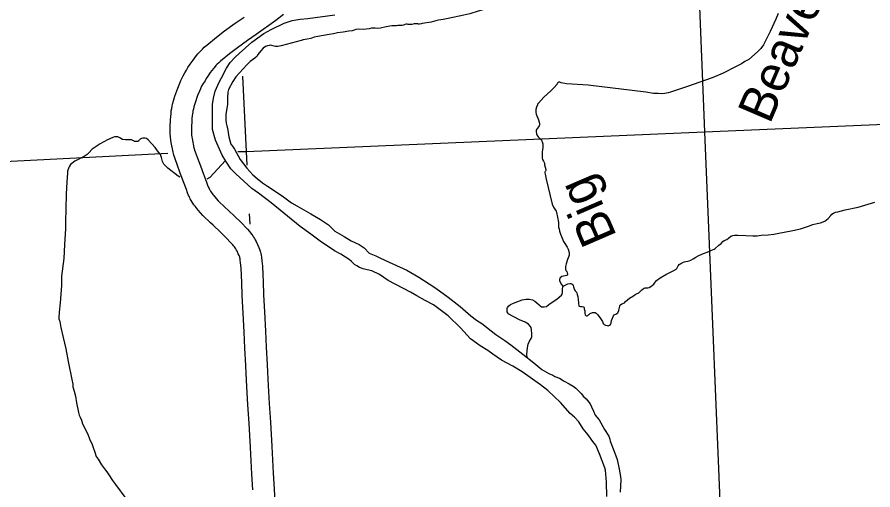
# Model space of a CAD drawing. Extents: x 1720274 to 1751788, y 372074 to 391887.
# Drawn here: x 1737987 to 1739571, y 379057 to 379933 of the extents above; entities that cross this region are included whole.
import ezdxf

# ---------------------------------------------------------------- set-up
doc = ezdxf.new("R2010")
doc.units = 0
for name, color, linetype in [('Level 10', 7, 'Continuous'), ('Level 35', 7, 'Continuous'), ('Level 5', 7, 'Continuous'), ('Level 9', 7, 'Continuous')]:
    doc.layers.add(name, color=color, linetype=linetype)

msp = doc.modelspace()

# ---------------------------------------------------------------- linework, layer by layer
at = {"layer": 'Level 10'}
for points in [[(1738479.8, 379937.6), (1738466, 379926.9), (1738429.6, 379900.7), (1738413.4, 379889.6), (1738394.6, 379875.9), (1738380.2, 379864.9), (1738363.6, 379851.3), (1738360.1, 379848.1), (1738357.5, 379845.6), (1738354.9, 379843), (1738351.4, 379839.2), (1738350.3, 379837.8), (1738344.5, 379830.1), (1738339.8, 379823.4), (1738336.9, 379819), (1738334.7, 379815.1), (1738331.5, 379809.7), (1738328.5, 379804.7), (1738327.1, 379802), (1738326.2, 379799.9), (1738324.4, 379795.6), (1738321.1, 379787.6), (1738316.6, 379774.2), (1738314.2, 379767), (1738313.2, 379762.5), (1738312.4, 379759.4), (1738311.9, 379757.1), (1738311.5, 379753.9), (1738311.1, 379750.7), (1738310.6, 379745.3), (1738310.3, 379741.3), (1738309.7, 379728.2), (1738309.7, 379717.9), (1738309.9, 379714.9), (1738310.4, 379710.7), (1738310.9, 379707.8), (1738314.3, 379691), (1738314.8, 379688.9), (1738315.1, 379687.7), (1738315.5, 379686.4), (1738316.6, 379683.2), (1738320.1, 379673.5), (1738326.1, 379657.2), (1738331.6, 379641.8), (1738337.2, 379627.3), (1738339.3, 379621.7), (1738340.6, 379618.4), (1738341.1, 379617.4), (1738342.2, 379615.3), (1738343.1, 379613.3), (1738343.4, 379612.7), (1738344, 379611.7), (1738344.9, 379610.3), (1738346.2, 379608.6), (1738347.9, 379606.3), (1738349.4, 379604.4), (1738351, 379602.2), (1738352.2, 379600.8), (1738359.1, 379592.7), (1738372.1, 379580.5), (1738377.3, 379575.5), (1738390.5, 379562.7), (1738400.2, 379553.4), (1738413.4, 379540.3), (1738417.1, 379535.7), (1738419, 379533.3), (1738421.2, 379530.3), (1738423.1, 379527.7), (1738424.6, 379525.3), (1738426.1, 379522.9), (1738427.8, 379520.1), (1738429.3, 379517.1), (1738432, 379511.8), (1738434.5, 379506.3), (1738435.7, 379503), (1738436.9, 379499.4), (1738437.5, 379497.2), (1738438.1, 379494.7), (1738438.6, 379492.2), (1738439.2, 379488.3), (1738440, 379481.7), (1738441, 379471.3), (1738441.9, 379456.1), (1738442.4, 379442.7)], [(1738402.9, 379441.1), (1738402.4, 379454.2), (1738401.7, 379468.2), (1738400.7, 379477.4), (1738400.1, 379482.6), (1738399.7, 379484.9), (1738399.4, 379486.8), (1738399.2, 379487.7), (1738399.1, 379487.9), (1738398.5, 379489.8), (1738398, 379491.1), (1738396.4, 379494.6), (1738394, 379499.3), (1738392.9, 379501.4), (1738392.4, 379502.3), (1738391.5, 379503.8), (1738390.3, 379505.6), (1738389.2, 379507.2), (1738387.7, 379509.2), (1738386.2, 379511.1), (1738384, 379513.8), (1738372.6, 379525.1), (1738363.1, 379534.2), (1738349.7, 379547.2), (1738344.8, 379552), (1738330.5, 379565.4), (1738321.8, 379575.5), (1738320, 379577.8), (1738318.1, 379580.2), (1738316.4, 379582.4), (1738314.2, 379585.4), (1738312.3, 379588), (1738310.9, 379590.2), (1738308.9, 379593.3), (1738307.4, 379596.4), (1738306.8, 379597.7), (1738305.7, 379599.7), (1738304.4, 379602.5), (1738302.4, 379607.4), (1738300.3, 379613.3), (1738294.6, 379628), (1738289, 379643.8), (1738283, 379660), (1738279.3, 379670.2), (1738278, 379673.9), (1738277.1, 379676.9), (1738276.3, 379680.1), (1738275.7, 379682.9), (1738272, 379700.7), (1738271.3, 379705.2), (1738270.6, 379711.2), (1738270.2, 379716.5), (1738270.1, 379729.1), (1738270.9, 379743.5), (1738271.2, 379748.4), (1738271.9, 379755.2), (1738272.3, 379759.1), (1738273, 379763.5), (1738273.8, 379767.7), (1738274.8, 379771.8), (1738276.2, 379777.7), (1738279.1, 379786.6), (1738284.1, 379801.5), (1738287.9, 379810.6), (1738289.8, 379815.3), (1738291.5, 379819.2), (1738294, 379824), (1738297.5, 379829.9), (1738300.5, 379834.9), (1738303.2, 379839.6), (1738307.1, 379845.5), (1738312.6, 379853.4), (1738319.1, 379862), (1738321.4, 379864.9), (1738326.2, 379870.1), (1738329.8, 379873.8), (1738333.3, 379877.1), (1738337.8, 379881.2), (1738355.7, 379895.8), (1738371, 379907.6), (1738390.6, 379921.8), (1738406.9, 379933)], [(1738423.2, 379056.9), (1738421.7, 379086.1), (1738418.8, 379135.3), (1738416.5, 379180.4), (1738414.3, 379214.4), (1738412.4, 379248.3), (1738411.2, 379272.7), (1738410.3, 379287.3), (1738408.5, 379319.7), (1738407.2, 379349.2), (1738405.4, 379384.7), (1738403.8, 379416.9), (1738402.9, 379441.1)], [(1738442.4, 379442.7), (1738443.3, 379418.6), (1738444.9, 379386.7), (1738446.6, 379351.1), (1738448, 379321.7), (1738449.7, 379289.6), (1738450.6, 379274.9), (1738451.8, 379250.4), (1738453.7, 379216.8), (1738455.9, 379182.8), (1738458.3, 379137.5), (1738461.1, 379088.3), (1738462.6, 379058.9), (1738464.5, 379021)]]:
    msp.add_lwpolyline(points, dxfattribs=at)
at = {"layer": 'Level 35'}
for points in [[(1739396.2, 379939.4), (1739391.8, 379929.2), (1739381, 379906.5), (1739371.9, 379887.5), (1739368.9, 379881.7), (1739363.9, 379874.8), (1739357.6, 379868.7), (1739341.8, 379854.6), (1739334.4, 379850.7), (1739328, 379846.6), (1739315.9, 379840), (1739294.1, 379829.2), (1739273.7, 379820.4), (1739228.1, 379804.6), (1739196.9, 379793.8), (1739192, 379792.7), (1739185.9, 379791.4), (1739180.1, 379790.8), (1739173.8, 379791.1), (1739165.2, 379791.6), (1739151.1, 379793.6), (1739044.1, 379807.1), (1739004, 379809.6), (1738994.4, 379811.2), (1738991.6, 379812.1), (1738990.4, 379812.3), (1738989.5, 379812.1), (1738987.8, 379811.4), (1738987, 379810.7), (1738985.9, 379808.2), (1738981.2, 379802.3), (1738974.7, 379795.6), (1738962.2, 379784.6), (1738952.2, 379773.4), (1738950.6, 379771.7), (1738950.1, 379770.1), (1738948.3, 379766.3), (1738947, 379761.8), (1738947, 379760.2), (1738947, 379759.5), (1738947.1, 379757), (1738948.1, 379752.9), (1738952.1, 379742.9), (1738953.6, 379738.1), (1738954, 379736.3), (1738954, 379734.6), (1738953.9, 379733), (1738953.3, 379731.2), (1738952.3, 379729.7), (1738950.2, 379727), (1738948.5, 379724.7), (1738948.1, 379722.8), (1738948, 379720.6), (1738948.4, 379716.4), (1738949.5, 379713.7), (1738951.4, 379711.2), (1738953.5, 379709.5), (1738956.3, 379706.7), (1738957.5, 379704.8), (1738959.7, 379699.8), (1738960.1, 379698.2), (1738960.1, 379695.4), (1738960.1, 379691.6), (1738959.5, 379686.8), (1738958.7, 379683.1), (1738958.8, 379680.5), (1738959, 379672.8), (1738959.2, 379671.3), (1738959.9, 379669.3), (1738961.6, 379666.2), (1738962.8, 379663.8), (1738963.2, 379662.3), (1738963.5, 379659.2), (1738964.4, 379655.2), (1738965.7, 379650.6), (1738965.7, 379649), (1738965.3, 379647.5), (1738964.4, 379646.6), (1738964, 379645.5), (1738964, 379644.5), (1738964.4, 379642.1), (1738966.7, 379632.8), (1738977.8, 379586.4), (1738979.9, 379581.1), (1738982.5, 379577.1), (1738984.7, 379573.2), (1738985.7, 379570.7), (1738987.4, 379562.2), (1738989.1, 379552.3), (1738989.5, 379543.7), (1738990.4, 379540.6), (1738991.3, 379536.3), (1738992.9, 379530.8)], [(1738287.9, 379636.7), (1738285.2, 379638.1), (1738265.9, 379653.2), (1738258.6, 379660.6), (1738256, 379665.3), (1738254.2, 379672.7), (1738252, 379678.2), (1738248.3, 379682.8), (1738242.1, 379691.4), (1738229.2, 379705.3), (1738226.2, 379707.8), (1738223.8, 379708.6), (1738221.9, 379708.8), (1738219.5, 379708.6), (1738216.9, 379708), (1738214.7, 379706.9), (1738213.9, 379706.1), (1738212.9, 379704.7), (1738212.1, 379703.7), (1738210.3, 379702.7), (1738209.6, 379702.5), (1738207.2, 379702.5), (1738204.4, 379702.7), (1738203, 379703.5), (1738201.2, 379704.3), (1738198.8, 379705.3), (1738197.8, 379705.5), (1738194.3, 379705.5), (1738191.1, 379705.5), (1738187.7, 379705.5), (1738181.8, 379706.3), (1738179, 379707.8), (1738176.8, 379709.2), (1738174.4, 379710.4), (1738173, 379711.2), (1738172.2, 379711.2), (1738169.2, 379711.2), (1738167.1, 379711), (1738164.1, 379709.8), (1738154.2, 379705.5), (1738140.3, 379697.9), (1738125.6, 379688), (1738119.6, 379681.6), (1738116.6, 379678.4), (1738110.7, 379674.9), (1738100, 379669.3), (1738093.4, 379666.1), (1738087.8, 379661.5), (1738085.9, 379659.6), (1738083.9, 379657), (1738082.7, 379654.4), (1738079.9, 379647.8), (1738079.9, 379643.7), (1738078.9, 379627.8), (1738077.5, 379605.1), (1738076.7, 379577.7), (1738076.3, 379554), (1738076.5, 379547.1), (1738076.1, 379540.5), (1738074.3, 379511.5), (1738073, 379485.5), (1738069.2, 379452.7), (1738069, 379446.7), (1738069, 379440.8), (1738069, 379435.8), (1738067.6, 379419.5), (1738066.2, 379403.6), (1738064.8, 379386.3), (1738064, 379376.4), (1738064.2, 379374.2), (1738065.8, 379368.8), (1738068, 379358.1), (1738072.2, 379339.4), (1738077.1, 379318.1), (1738081.3, 379294.7), (1738088.4, 379261.5), (1738090.2, 379252.8), (1738090.2, 379248), (1738092.2, 379239.8), (1738094.6, 379230.5), (1738096.8, 379218.2), (1738100.4, 379200.7), (1738101.5, 379195.7), (1738103.3, 379192), (1738105.9, 379186), (1738107.9, 379179.2), (1738118, 379160.2), (1738120.8, 379151.4), (1738126, 379140.9), (1738127.7, 379135.5), (1738130.5, 379127), (1738133.3, 379118.8), (1738136.7, 379113.7)], [(1738372.5, 379667.1), (1738343.4, 379635.9), (1738338.3, 379632.4)], [(1739092.5, 379381.1), (1739095.6, 379382.6), (1739098.9, 379385.2), (1739101.1, 379389.4), (1739101.6, 379392.4), (1739102.6, 379397.3), (1739103.1, 379398.7), (1739104.1, 379399.8), (1739106.4, 379401.5), (1739108.2, 379402.2), (1739111.4, 379403.5), (1739113.5, 379405.8), (1739120.5, 379412.3), (1739128.4, 379416.6), (1739131.1, 379418.9), (1739133.4, 379420.5), (1739138, 379422.4), (1739140.3, 379424.7), (1739143.5, 379427.7), (1739145.8, 379429.8), (1739148.1, 379430.8), (1739149.8, 379431.2), (1739151.8, 379431.2), (1739154.4, 379431.2), (1739156.9, 379432.2), (1739160, 379433.6), (1739165.7, 379438.3), (1739167.2, 379439.8), (1739170.8, 379445.1), (1739177.3, 379449.9), (1739187.9, 379456), (1739201.8, 379463.1), (1739207.2, 379466), (1739208.4, 379467.3), (1739211, 379472.4), (1739212.9, 379474.9), (1739215.5, 379476.4), (1739221.8, 379479.6), (1739225.1, 379480.2), (1739228.6, 379480.7), (1739231.1, 379481.5), (1739234.4, 379482.5), (1739238.7, 379485.2), (1739243.5, 379488.2), (1739247.6, 379490.7), (1739254.9, 379494), (1739267.3, 379498.4), (1739271.5, 379500.6), (1739277.4, 379502.8), (1739279.4, 379504.4), (1739286.2, 379510.7), (1739290.3, 379513.5), (1739293.7, 379517.5), (1739296, 379519.2), (1739300.9, 379521), (1739303.9, 379523.5), (1739308.6, 379527), (1739311.9, 379528.4), (1739314.9, 379528.9), (1739321, 379528.8), (1739336, 379528.1), (1739349, 379527.9), (1739357.1, 379527.9), (1739364.7, 379528.9), (1739377.3, 379529.6), (1739388, 379530.6), (1739394.2, 379532.1), (1739423, 379537.7), (1739437.4, 379540.5), (1739444.7, 379543), (1739452.3, 379545.8), (1739459.9, 379548.7), (1739462.4, 379549.2), (1739468.2, 379550.3), (1739474.5, 379551.6), (1739482.1, 379554.6), (1739488.4, 379559.6), (1739493.8, 379565.2), (1739495.3, 379567.7), (1739498.2, 379569.5), (1739502, 379571.4), (1739506.4, 379572.2), (1739520.2, 379575.8), (1739544.2, 379580.8), (1739574.8, 379590.1)], [(1738992.9, 379530.8), (1738995.9, 379523.6), (1738998.4, 379517.1), (1739000.9, 379513.3), (1739005.4, 379506.5), (1739007, 379503.1), (1739008.4, 379498.8), (1739009, 379495.7), (1739008.8, 379492.1), (1739008.4, 379489.9), (1739005.6, 379484), (1739003.2, 379475.9), (1739002.1, 379470.7), (1739001.9, 379468.5), (1739002.2, 379466.5), (1739003, 379463.5), (1739004.6, 379461.4), (1739005.3, 379459.3), (1739005.7, 379456.5), (1739005.6, 379455.6), (1739005, 379454.6), (1739004, 379454.1), (1739001.3, 379453.4), (1738998.8, 379453.1), (1738995.6, 379452.1), (1738991.9, 379449.3), (1738991.5, 379448.3), (1738991.2, 379446.6), (1738991.3, 379444.9), (1738992.3, 379442.1), (1738994.6, 379437.3), (1738996.4, 379435.3), (1738997.8, 379433.2)], [(1738931, 379302.6), (1738930.8, 379308.7), (1738931.8, 379320.5), (1738933.2, 379327.3), (1738935.7, 379332.5), (1738938.9, 379337.4), (1738940.1, 379340.5), (1738940.1, 379343.2), (1738940.1, 379346.4), (1738939.3, 379353.5), (1738938.6, 379357.7), (1738936.7, 379360.6), (1738933.5, 379363.8), (1738927.6, 379368), (1738917.3, 379372.1), (1738896, 379383.4), (1738895.3, 379385.1), (1738894.3, 379386.8), (1738894.1, 379388.8), (1738894.1, 379393), (1738894.8, 379395.2), (1738897, 379398.1), (1738900.4, 379400.6), (1738906.1, 379403.2), (1738922.2, 379409.4), (1738929.1, 379410.3), (1738935.7, 379410.1), (1738941.3, 379409.1), (1738945.5, 379406.4), (1738949.1, 379403.7), (1738953.3, 379400.1), (1738955.5, 379398.1), (1738957.9, 379396.1), (1738959.4, 379396.1), (1738962.4, 379395.9), (1738966.8, 379396.9), (1738971.6, 379400.3), (1738986.6, 379410.8), (1738994.7, 379417.7), (1738996.3, 379419.7), (1738996.9, 379423), (1738996.9, 379426.2), (1738996.9, 379428.3), (1738996.9, 379430.2), (1738997.3, 379432.5), (1738999.1, 379434.8), (1739006.4, 379438.6), (1739010.3, 379439.1), (1739012, 379439.1), (1739014.2, 379438.6), (1739015.5, 379437.5), (1739016.6, 379435.8), (1739017.3, 379433.1), (1739018.6, 379427.5), (1739019.8, 379426), (1739022.4, 379423.4), (1739023.3, 379421.7), (1739024.1, 379419.1), (1739024.8, 379415.4), (1739025.6, 379409.1), (1739026.1, 379404.1), (1739026.1, 379401.7), (1739026.6, 379399.3), (1739027.1, 379398.3), (1739027.7, 379397.5), (1739029.7, 379396.8), (1739033.2, 379396.8), (1739035.4, 379396), (1739036.5, 379394.7), (1739037, 379392.7), (1739038.3, 379388.7), (1739038.2, 379383.8), (1739038.8, 379381.4), (1739040, 379380.3), (1739041.1, 379379.8), (1739042.5, 379379.8), (1739043.5, 379380.4), (1739045.3, 379381.8), (1739046.6, 379382.8), (1739047.9, 379383.8), (1739049.1, 379384.3), (1739050.9, 379385.2), (1739052.4, 379385.4), (1739055.2, 379385.6), (1739056.9, 379385.4), (1739058.7, 379384.6), (1739062.2, 379381.4), (1739066.8, 379374.6), (1739070.5, 379369), (1739071.9, 379365.4), (1739073.9, 379363.7), (1739076.2, 379362), (1739079.2, 379361.4), (1739081.5, 379361.2), (1739083.7, 379362.2), (1739085.4, 379363.5), (1739086.8, 379366.4), (1739087.2, 379370.7), (1739089.2, 379375), (1739091, 379379.6), (1739092.5, 379381.1)], [(1738136.7, 379113.7), (1738143.2, 379103.7), (1738150.2, 379093.8), (1738152.8, 379090.6), (1738156.7, 379085.2), (1738163.7, 379074.3), (1738169.2, 379067), (1738188.1, 379040.9)]]:
    msp.add_lwpolyline(points, dxfattribs=at)
at = {"layer": 'Level 5'}
for points in [[(1739226, 380552.9), (1739259.5, 379720.3)], [(1738404.4, 379823.6), (1738411, 379684)], [(1739259.5, 379720.3), (1739651.6, 379737)], [(1738411, 379684), (1739259.5, 379720.3)], [(1739259.5, 379720.3), (1739295, 378873.3)], [(1738395.5, 379684), (1738411, 379684)], [(1738411, 379684), (1738412.3, 379658.8)], [(1737600.1, 379646.9), (1738266, 379680.7)], [(1738416.6, 379568.6), (1738417.6, 379549.4)]]:
    msp.add_lwpolyline(points, dxfattribs=at)
at = {"layer": 'Level 9'}
for points in [[(1738530.7, 379530.9), (1738510.7, 379545.3), (1738457, 379588.7), (1738433.7, 379606.5), (1738421.4, 379615.5), (1738391.5, 379642.4), (1738382.8, 379651.6), (1738373.2, 379666), (1738366.7, 379677.2), (1738354.1, 379704.7), (1738348.4, 379724.9), (1738348.3, 379747.9), (1738348.3, 379771.1), (1738350.3, 379782.5), (1738353.4, 379795.9), (1738360.9, 379812.5), (1738365, 379820.4), (1738374.3, 379838.2), (1738381.1, 379848.9), (1738390.6, 379858.8), (1738397.9, 379865.8), (1738421.1, 379886.6), (1738443.9, 379902.3), (1738457.5, 379910), (1738481.5, 379921.6), (1738495.9, 379926.8), (1738511, 379929.2), (1738525.1, 379930.3), (1738575.2, 379937)], [(1738874.3, 379950.9), (1738851.9, 379946.9), (1738840.3, 379944), (1738825.2, 379939.3), (1738814.2, 379936.8), (1738784.9, 379930.5), (1738775.4, 379928.4), (1738766.8, 379927.1), (1738761.8, 379926.1), (1738753.5, 379923.3), (1738736.9, 379920.9)], [(1738736.9, 379920.9), (1738735.2, 379920.4), (1738732, 379919.9), (1738730, 379919.9), (1738729, 379920.3), (1738726.9, 379920.6), (1738724.1, 379920.6), (1738721.8, 379920.5), (1738717.4, 379919.1), (1738715.1, 379919), (1738712.9, 379919.1), (1738710.6, 379919.5), (1738708.9, 379919.8), (1738707.2, 379919.7), (1738704.7, 379919.1), (1738702.2, 379917.9), (1738699.5, 379917.4), (1738695.7, 379917.4), (1738692, 379917.5), (1738689.2, 379917), (1738686.3, 379916.7), (1738683.4, 379916.6), (1738680.6, 379916.5), (1738677.2, 379915.9), (1738670.3, 379914.7), (1738659.7, 379912.4), (1738655, 379911.9), (1738649.6, 379912.2), (1738646.2, 379912.7), (1738642.7, 379912.3), (1738638.6, 379911.4), (1738633, 379910.6), (1738628.5, 379910.2), (1738618.1, 379910.5), (1738614.1, 379909.9), (1738611.1, 379908.9), (1738607.1, 379907.3), (1738601.3, 379906.7), (1738590.6, 379905.1), (1738579.8, 379903.7), (1738572.8, 379902), (1738564.8, 379900.8), (1738543.8, 379897.1), (1738536.6, 379895.5), (1738530.4, 379893.5), (1738523.7, 379892.2), (1738516.6, 379890.8), (1738512.6, 379889.8), (1738475.8, 379879.7), (1738469.7, 379878.7), (1738465.1, 379878.7), (1738462.8, 379879.2), (1738458.6, 379880.2), (1738455.6, 379880.8), (1738453.5, 379880.6), (1738450.4, 379879.8), (1738446.9, 379878.3), (1738442.6, 379875.4), (1738437.8, 379870.6), (1738432.7, 379863.8), (1738431, 379860.6), (1738426.7, 379856.8), (1738418.6, 379850.4), (1738412, 379844.3), (1738391.6, 379822.1), (1738386.3, 379813.5), (1738378, 379798.7), (1738377.2, 379794.1), (1738376.5, 379783.6), (1738376.1, 379771.8), (1738373.4, 379752.6), (1738373.5, 379741.9), (1738373.9, 379736.6), (1738375.2, 379731.2), (1738376.2, 379727), (1738378.7, 379710.9), (1738382.5, 379697.8), (1738385.4, 379693.7), (1738389.1, 379688), (1738399.9, 379669.2), (1738412.2, 379653.2), (1738423.1, 379640.7), (1738431.1, 379634.1), (1738441.2, 379625.7), (1738450.2, 379619.5)], [(1738450.2, 379619.5), (1738477.8, 379601.9), (1738495.1, 379588.9), (1738504.7, 379583), (1738530.5, 379568.5), (1738548.6, 379558.2), (1738563.5, 379548.2)], [(1738563.5, 379548.2), (1738575, 379536.3), (1738592.1, 379526.5), (1738605.5, 379518.4), (1738620.2, 379511.5), (1738629.1, 379505.4), (1738638.7, 379495.4), (1738651.1, 379490.5), (1738659.6, 379486.6), (1738682.4, 379475.8), (1738708.3, 379464.4), (1738730.6, 379451.4), (1738749.9, 379439), (1738761.9, 379430.5), (1738784.8, 379413.8), (1738807.1, 379397), (1738827, 379379.8), (1738837.1, 379371.7), (1738847.1, 379365), (1738872.9, 379345.1), (1738890.1, 379333.9), (1738901, 379325.9), (1738922.9, 379308.4), (1738943.3, 379292.4), (1738958.5, 379280.3), (1738971.1, 379272.7), (1738978.5, 379269.8), (1738982.6, 379267.1), (1738991, 379264), (1738996.3, 379261.2), (1739000, 379258.7), (1739008.9, 379253.7), (1739016.6, 379248.9), (1739021.1, 379245.2), (1739025.5, 379241.4), (1739030.9, 379235.6), (1739035.7, 379230.3), (1739040.5, 379225.7), (1739048, 379216.7), (1739050.5, 379210.9), (1739053.9, 379202.7), (1739057.2, 379195.6), (1739064.6, 379186.9), (1739074.5, 379168.8), (1739082.6, 379156.3), (1739084.3, 379151.2), (1739085, 379147.5), (1739091.7, 379129.8), (1739095.3, 379120.4), (1739097.9, 379113.3), (1739101.3, 379095.7), (1739104.3, 379081.9), (1739104.8, 379075.6), (1739103.3, 379052.6)], [(1739078.8, 379044.5), (1739078.1, 379071.3), (1739076.5, 379093.4), (1739075.1, 379097.9), (1739065.2, 379123.7), (1739058.2, 379140), (1739055.2, 379143.9), (1739050.9, 379149.4), (1739047.4, 379154.6), (1739040.9, 379162.8), (1739034.7, 379169.9), (1739026.6, 379183), (1739019.1, 379192), (1739010.6, 379198.6), (1738992.7, 379218.8), (1738969.3, 379240.9), (1738956.2, 379251.7), (1738922.1, 379275.6), (1738904.6, 379286.2), (1738883.9, 379297.2), (1738867.5, 379308.6), (1738858.1, 379315), (1738844.1, 379324), (1738826.5, 379336.9), (1738807.9, 379357.5), (1738784.9, 379379.7), (1738757.6, 379399.9), (1738742.2, 379407.9), (1738726.8, 379416.5), (1738715.1, 379423.1), (1738673.8, 379445.2), (1738657.8, 379456), (1738643.5, 379462.8), (1738635.1, 379464.9), (1738627.5, 379466.8), (1738620.8, 379468.9), (1738616, 379471.9), (1738611.3, 379474.7), (1738605.9, 379480.1), (1738601.5, 379483.8), (1738594.9, 379487.9), (1738586, 379493.6), (1738574.2, 379500.1), (1738547.8, 379517.6), (1738530.7, 379530.9)]]:
    msp.add_lwpolyline(points, dxfattribs=at)

# ---------------------------------------------------------------- texts
at = {"layer": 'Level 35'}
for s, rotation, p in [('Beaver', 66.7627, (1739380.5, 379733.1)), ('Big', 113.3893, (1739097.9, 379526.8))]:
    msp.add_text(s, height=66.74, rotation=rotation, dxfattribs=at).set_placement(p)

doc.saveas('drawing.dxf')
